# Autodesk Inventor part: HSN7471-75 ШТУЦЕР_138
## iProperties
Created: 2011-02
Part Number: HSN7471-75 ШТУЦЕР_138
Document SubType Name: Modeling
Designer: Чернышев Юрий
Mass: 7.44894 g
Surface Area: 61.9289 cm^2
Volume: 7.44894 cm^3
Density: 1 g/cm^3
Author: Чернышев Юрий
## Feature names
1. ExtrusionBlind1
2. ExtrusionBlind2
3. RevolutionAngle1
4. RevolutionAngle2
5. ExtrusionBlind3
6. ExtrusionBlind4
7. Hole1
